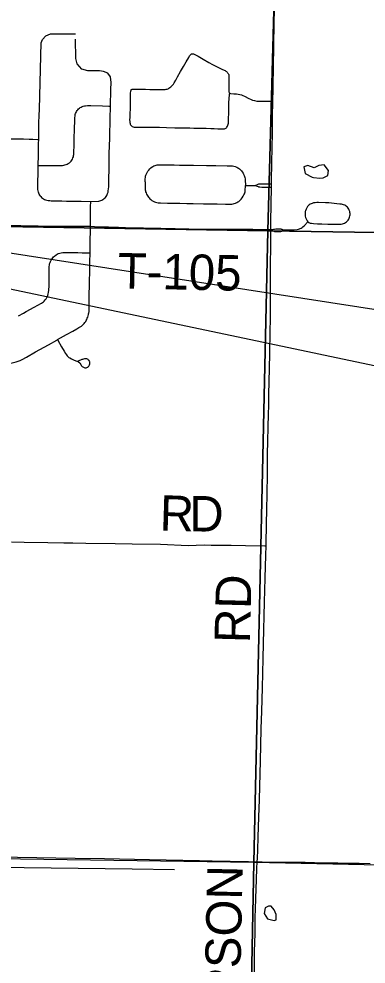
# Model space of a CAD drawing. Extents: x 0 to 34, y 0 to 22.
# Drawn here: x 5.051 to 5.608, y 14.756 to 16.271 of the extents above; entities that cross this region are included whole.
import ezdxf

# ---------------------------------------------------------------- set-up
doc = ezdxf.new("R2010")
doc.units = 0
for name, color, linetype in [('GM_X_Corporation', 7, 'Continuous'), ('GM_X_County_Road', 7, 'Continuous'), ('GM_X_Minor_Lake', 7, 'Continuous'), ('GM_X_Minor_River', 7, 'Continuous'), ('GM_X_Township_Road', 7, 'Continuous'), ('GM_X_Township_Road_Text', 7, 'Continuous'), ('SH_Text', 7, 'Continuous')]:
    doc.layers.add(name, color=color, linetype=linetype)

msp = doc.modelspace()

# ---------------------------------------------------------------- linework, layer by layer
at = {"layer": 'GM_X_Corporation'}
for points in [[(4.4576, 16.9688), (5.4784, 16.9512), (5.4509, 15.9313), (4.4354, 15.9477)], [(5.4784, 16.9512), (6.4745, 16.9262), (6.4581, 15.916), (5.4509, 15.9313)], [(4.4354, 15.9477), (5.4509, 15.9313), (5.428, 14.9189), (4.4167, 14.9334)], [(5.4509, 15.9313), (6.4581, 15.916), (6.4397, 14.8975), (5.428, 14.9189)], [(4.4016, 14.1), (5.4122, 14.1), (5.428, 14.9189), (4.4167, 14.9334)], [(5.4122, 14.1), (6.4222, 14.1), (6.4397, 14.8975), (5.428, 14.9189)]]:
    msp.add_lwpolyline(points, close=True, dxfattribs=at)
at = {"layer": 'GM_X_County_Road'}
for points in [[(4.6352, 14.9342), (4.6708, 14.9336), (4.6925, 14.9331), (4.7124, 14.9327), (4.7317, 14.9325), (4.7628, 14.932), (4.8187, 14.9312), (4.8448, 14.9309), (4.8865, 14.9303), (4.9226, 14.9299), (4.9574, 14.9294), (5.0171, 14.9284), (5.0494, 14.9276), (5.1414, 14.9258), (5.1886, 14.9251), (5.2607, 14.9239), (5.3409, 14.922), (5.3614, 14.9216), (5.4198, 14.9204), (5.4337, 14.9202)], [(5.4337, 14.9202), (5.4416, 14.9201), (5.459, 14.9197), (5.4764, 14.9195), (5.4938, 14.9193), (5.5106, 14.9192), (5.5404, 14.9186), (5.5628, 14.9184), (5.5758, 14.9181), (5.597, 14.9176), (5.615, 14.9172)]]:
    msp.add_lwpolyline(points, dxfattribs=at)
at = {"layer": 'GM_X_Minor_Lake'}
for p, q in [((5.5239, 16.0167), (5.5339, 16.0159)), ((5.4639, 14.8356), (5.4606, 14.8429))]:
    msp.add_line(p, q, dxfattribs=at)
for points in [[(5.5339, 16.0159), (5.5397, 16.0161), (5.5469, 16.0198), (5.5481, 16.0282), (5.5411, 16.037), (5.5327, 16.0359), (5.5248, 16.0322), (5.5146, 16.0362), (5.5082, 16.0336), (5.5107, 16.0233), (5.5216, 16.0171), (5.5239, 16.0167)], [(5.4606, 14.8429), (5.4561, 14.849), (5.4519, 14.8491), (5.4462, 14.8461), (5.4446, 14.8374), (5.4502, 14.8286), (5.4611, 14.8258), (5.4641, 14.8269), (5.4639, 14.8356)]]:
    msp.add_lwpolyline(points, dxfattribs=at)
at = {"layer": 'GM_X_Minor_River'}
msp.add_lwpolyline([(4.5825, 14.9176), (4.8159, 14.9147), (4.9205, 14.913), (5.0599, 14.9109), (5.2329, 14.9087), (5.3008, 14.9079)], dxfattribs=at)
at = {"layer": 'GM_X_Township_Road'}
for p, q in [((5.1982, 16.1312), (5.1986, 16.1577)), ((5.4148, 16.0038), (5.4305, 16.0039))]:
    msp.add_line(p, q, dxfattribs=at)
for points in [[(5.4589, 16.1391), (5.4593, 16.1587), (5.4598, 16.1991), (5.4602, 16.2227), (5.461, 16.2687), (5.4617, 16.2942), (5.4621, 16.3079), (5.4623, 16.3178), (5.4625, 16.334), (5.4626, 16.3496), (5.4629, 16.3682), (5.4631, 16.3769), (5.4633, 16.383), (5.4638, 16.3872), (5.4646, 16.3905), (5.468, 16.4019)], [(5.0831, 16.0778), (5.0833, 16.0954), (5.0836, 16.1041), (5.0841, 16.1159), (5.0844, 16.126), (5.0872, 16.2325), (5.0891, 16.238), (5.0948, 16.2438), (5.102, 16.2468), (5.1422, 16.2468)], [(5.1986, 16.1577), (5.1993, 16.1688), (5.1983, 16.1779), (5.194, 16.1842), (5.1872, 16.1867), (5.1809, 16.1877), (5.1619, 16.1876), (5.1525, 16.1901), (5.1449, 16.1989), (5.1426, 16.2076), (5.1423, 16.2383)], [(5.2315, 16.1576), (5.2329, 16.1581), (5.2344, 16.1584), (5.2363, 16.1584), (5.2385, 16.1584), (5.2447, 16.1583), (5.2484, 16.1582), (5.2509, 16.1582), (5.2547, 16.1581), (5.2615, 16.158), (5.2683, 16.1578), (5.2733, 16.1577), (5.2782, 16.1577), (5.2832, 16.1577), (5.2858, 16.1578), (5.2877, 16.1581), (5.289, 16.1584), (5.2909, 16.1591), (5.292, 16.1597), (5.2937, 16.1608), (5.2952, 16.162), (5.2966, 16.1634), (5.2979, 16.1648), (5.2991, 16.1664), (5.3005, 16.1685), (5.3029, 16.1729), (5.3059, 16.1783), (5.3106, 16.1864), (5.3152, 16.1945), (5.3174, 16.1983), (5.3195, 16.202), (5.3237, 16.2091), (5.3251, 16.2115), (5.326, 16.2127), (5.327, 16.2137), (5.3276, 16.2142), (5.3282, 16.2147), (5.3293, 16.2152)], [(5.3293, 16.2152), (5.3303, 16.2151), (5.331, 16.215), (5.3317, 16.2148), (5.3324, 16.2145), (5.3335, 16.214), (5.3344, 16.2135), (5.3388, 16.2111), (5.3468, 16.2063), (5.356, 16.2012), (5.362, 16.1979), (5.3736, 16.1919), (5.378, 16.1898), (5.382, 16.188), (5.3832, 16.1873), (5.3843, 16.1866), (5.3853, 16.1857), (5.3862, 16.1847), (5.387, 16.1836), (5.3876, 16.1823), (5.3879, 16.1817), (5.3881, 16.1803), (5.3882, 16.1784), (5.3881, 16.1715), (5.3881, 16.1647), (5.3881, 16.1603), (5.3881, 16.1566), (5.3882, 16.1548), (5.3883, 16.1538), (5.3887, 16.1528), (5.3896, 16.1518)], [(5.2315, 16.1576), (5.2308, 16.1564), (5.2304, 16.1547), (5.2301, 16.1526), (5.2298, 16.1458), (5.2297, 16.1415), (5.2297, 16.1371), (5.2296, 16.1315), (5.2296, 16.1272), (5.2294, 16.119), (5.2293, 16.116), (5.2292, 16.1128), (5.229, 16.1091), (5.2291, 16.1067), (5.2294, 16.105), (5.2298, 16.1033), (5.2301, 16.1022), (5.2306, 16.1012), (5.2312, 16.1002), (5.232, 16.0994), (5.2332, 16.0985), (5.2348, 16.0979), (5.2365, 16.0976), (5.2412, 16.0975), (5.2458, 16.0974), (5.2526, 16.0973), (5.2625, 16.0972), (5.2718, 16.0973), (5.2768, 16.0973), (5.288, 16.0968), (5.3017, 16.0965), (5.3116, 16.0964), (5.3185, 16.0962), (5.3253, 16.0961), (5.3321, 16.096), (5.3408, 16.0959), (5.352, 16.0957), (5.3595, 16.0955), (5.3645, 16.0953), (5.3707, 16.0949), (5.3787, 16.0945), (5.3799, 16.0945), (5.3814, 16.0948), (5.3824, 16.0953), (5.3834, 16.0959), (5.3842, 16.0966), (5.3849, 16.0974), (5.3858, 16.0989), (5.3866, 16.1005), (5.3872, 16.1022), (5.3875, 16.1039), (5.3877, 16.1056), (5.3878, 16.1081), (5.3882, 16.123), (5.3882, 16.1292), (5.3882, 16.1325), (5.3881, 16.1354), (5.3883, 16.1387), (5.3884, 16.1411), (5.3886, 16.1452), (5.389, 16.1478), (5.3894, 16.1506), (5.3896, 16.1518)], [(5.3896, 16.1518), (5.391, 16.1512), (5.3964, 16.151), (5.4002, 16.1507), (5.4033, 16.1503), (5.4058, 16.1498), (5.4083, 16.1491), (5.4107, 16.1482), (5.4135, 16.1469), (5.4201, 16.1433), (5.4229, 16.1421), (5.424, 16.1416), (5.4263, 16.1408), (5.4292, 16.14), (5.4328, 16.1393), (5.4364, 16.139), (5.4401, 16.1389), (5.445, 16.1389), (5.4513, 16.139), (5.4589, 16.1391)], [(5.4564, 16.0013), (5.4565, 16.0064), (5.4567, 16.0131), (5.4571, 16.0386), (5.4577, 16.0666), (5.458, 16.0859), (5.4584, 16.1139), (5.4589, 16.1391)], [(5.0824, 16.0361), (5.0853, 16.0361), (5.1008, 16.0362), (5.1183, 16.036), (5.1214, 16.0361), (5.1234, 16.0364), (5.1253, 16.0368), (5.1271, 16.0374), (5.1289, 16.0382), (5.1306, 16.0391), (5.1323, 16.0402), (5.1337, 16.0415), (5.1351, 16.043), (5.1363, 16.0446), (5.1372, 16.0463), (5.138, 16.048), (5.1387, 16.0499), (5.1392, 16.0518), (5.1395, 16.0537), (5.1397, 16.0569), (5.1399, 16.0687), (5.1401, 16.0749), (5.1403, 16.0825), (5.1405, 16.0912), (5.1406, 16.0954), (5.1409, 16.1078), (5.1411, 16.1127), (5.1414, 16.1151), (5.1418, 16.1175), (5.1424, 16.1192), (5.143, 16.1209), (5.1438, 16.1224), (5.1448, 16.1239), (5.1459, 16.1253), (5.1471, 16.1266), (5.1485, 16.1277), (5.1499, 16.1288), (5.1514, 16.1297), (5.153, 16.1305), (5.1547, 16.1311), (5.1564, 16.1315), (5.1582, 16.1318), (5.1612, 16.1319), (5.1668, 16.132), (5.1854, 16.1316), (5.1955, 16.1313), (5.1982, 16.1312)], [(5.1666, 15.9783), (5.1795, 15.9788), (5.1812, 15.9792), (5.1829, 15.9798), (5.1845, 15.9805), (5.1861, 15.9814), (5.1875, 15.9824), (5.1889, 15.9836), (5.1901, 15.9849), (5.1912, 15.9862), (5.1922, 15.9877), (5.1931, 15.9893), (5.1937, 15.9909), (5.1944, 15.9932), (5.1948, 15.9956), (5.1952, 15.9986), (5.1954, 16.0017), (5.1958, 16.0191), (5.196, 16.0259), (5.196, 16.029), (5.1962, 16.0411), (5.1964, 16.0552), (5.1971, 16.08), (5.198, 16.1129), (5.1982, 16.1291), (5.1982, 16.1312)], [(5.0264, 16.079), (5.0282, 16.079), (5.0369, 16.0788), (5.0437, 16.0788), (5.0522, 16.0786)], [(5.0522, 16.0786), (5.0585, 16.0785), (5.0676, 16.0782), (5.074, 16.0781), (5.0814, 16.0778), (5.0831, 16.0778)], [(5.0824, 16.0361), (5.0824, 16.0388), (5.0826, 16.05), (5.083, 16.0711), (5.0831, 16.0778)], [(5.0864, 15.9864), (5.0849, 15.9885), (5.0839, 15.9901), (5.0831, 15.9918), (5.0826, 15.9935), (5.0822, 15.9954), (5.0819, 15.9974), (5.0816, 16.0009), (5.0816, 16.0053), (5.0822, 16.0276), (5.0824, 16.0361)], [(5.2538, 16.0098), (5.2539, 16.0115), (5.2539, 16.0145), (5.2542, 16.0169), (5.2545, 16.0187), (5.255, 16.0204), (5.2559, 16.0226), (5.2569, 16.0248), (5.2582, 16.0268), (5.2597, 16.0287), (5.2613, 16.0305), (5.263, 16.0321), (5.2649, 16.0336), (5.2664, 16.0345), (5.268, 16.0353), (5.2697, 16.036), (5.2714, 16.0365), (5.2731, 16.0368), (5.2755, 16.0371), (5.2792, 16.0373), (5.2841, 16.0372), (5.2925, 16.037), (5.3002, 16.0368), (5.3089, 16.0367), (5.3313, 16.0364), (5.3523, 16.0361), (5.3673, 16.0359), (5.3853, 16.0357), (5.3909, 16.0356), (5.3939, 16.0353), (5.3962, 16.0348), (5.3985, 16.0342), (5.4007, 16.0333), (5.4023, 16.0324), (5.4038, 16.0315), (5.4052, 16.0304), (5.4066, 16.0292), (5.4082, 16.0275), (5.4097, 16.0256), (5.4111, 16.0236), (5.4119, 16.0221), (5.4129, 16.0199), (5.4135, 16.0182), (5.4139, 16.0165), (5.4143, 16.0147), (5.4145, 16.0128), (5.4148, 16.0038)], [(5.2538, 16.0098), (5.2539, 16.0033), (5.254, 15.9997), (5.2541, 15.9972), (5.2543, 15.9955), (5.2547, 15.9937), (5.2553, 15.9921), (5.2563, 15.9899), (5.2581, 15.9867), (5.2591, 15.9852), (5.2602, 15.9839), (5.2614, 15.9826), (5.2628, 15.9814), (5.2647, 15.98), (5.2668, 15.9789), (5.269, 15.9779), (5.2707, 15.9772), (5.2724, 15.9768), (5.2747, 15.9764), (5.2784, 15.9761), (5.2895, 15.9757), (5.3007, 15.9757), (5.3093, 15.9755), (5.3206, 15.9752), (5.3309, 15.975), (5.3473, 15.9748), (5.364, 15.9746), (5.3696, 15.9746), (5.3827, 15.9742), (5.3907, 15.9741), (5.393, 15.9742), (5.3949, 15.9745), (5.3966, 15.9749), (5.3989, 15.9757), (5.4011, 15.9766), (5.4027, 15.9775), (5.4041, 15.9784), (5.4055, 15.9795), (5.4068, 15.9808), (5.408, 15.9821), (5.4095, 15.984), (5.4112, 15.9866), (5.4123, 15.9887), (5.413, 15.9903), (5.4136, 15.992), (5.4141, 15.9937), (5.4143, 15.9954), (5.4148, 16.0038)], [(5.4305, 16.0039), (5.4354, 16.0061), (5.4365, 16.0065), (5.4372, 16.0066), (5.4379, 16.0066), (5.4404, 16.0066), (5.4441, 16.0066), (5.4506, 16.0065), (5.4565, 16.0064)], [(5.4305, 16.0039), (5.4351, 16.0021), (5.4359, 16.0018), (5.4366, 16.0016), (5.4378, 16.0016), (5.441, 16.0015), (5.4465, 16.0015), (5.4508, 16.0014), (5.4564, 16.0013)], [(5.4554, 15.9333), (5.4554, 15.946), (5.4564, 16.0013)], [(5.0864, 15.9864), (5.0878, 15.9849), (5.0894, 15.9836), (5.0909, 15.9825), (5.0925, 15.9816), (5.0943, 15.9809), (5.0961, 15.9804), (5.0985, 15.98), (5.101, 15.9797), (5.1034, 15.9795), (5.1103, 15.9793), (5.1158, 15.9792), (5.1202, 15.9791), (5.1277, 15.979), (5.1376, 15.9788), (5.1445, 15.9787), (5.1513, 15.9787), (5.1666, 15.9783)], [(5.1659, 15.9386), (5.166, 15.9404), (5.1664, 15.9519), (5.1664, 15.9572), (5.1665, 15.9648), (5.1665, 15.9696), (5.1666, 15.9783)], [(5.5151, 15.9458), (5.5166, 15.9448), (5.5186, 15.9438), (5.5207, 15.9434), (5.5237, 15.943), (5.5305, 15.9425), (5.5374, 15.9423), (5.5467, 15.9421), (5.556, 15.9418), (5.5591, 15.9419), (5.5634, 15.942), (5.5665, 15.942), (5.5684, 15.9422), (5.5702, 15.9425), (5.572, 15.943), (5.5737, 15.9437), (5.5754, 15.9446), (5.5769, 15.9457), (5.5782, 15.9469), (5.5794, 15.9484), (5.5804, 15.9499), (5.5813, 15.9516), (5.5819, 15.9533), (5.5824, 15.9552), (5.5826, 15.957), (5.5826, 15.9589), (5.5824, 15.9607), (5.582, 15.9625), (5.5814, 15.9643), (5.5806, 15.966), (5.5796, 15.9675), (5.5784, 15.969), (5.5771, 15.9703), (5.5756, 15.9714), (5.574, 15.9724), (5.5723, 15.9731), (5.5705, 15.9736), (5.5687, 15.974), (5.5662, 15.9742), (5.5615, 15.9747), (5.5483, 15.976), (5.5434, 15.9763), (5.5322, 15.9767), (5.5291, 15.9767), (5.5264, 15.9764), (5.5238, 15.9759), (5.522, 15.9753), (5.5202, 15.9746), (5.5185, 15.9738), (5.5169, 15.9728), (5.5155, 15.9716), (5.5144, 15.9702), (5.5137, 15.9691), (5.5121, 15.9658), (5.5111, 15.9635), (5.5108, 15.9623), (5.5105, 15.9604), (5.5104, 15.9585), (5.5105, 15.9566), (5.5107, 15.9547), (5.5112, 15.9529), (5.5116, 15.9517), (5.5127, 15.9495), (5.514, 15.9474), (5.5151, 15.9458)], [(5.0242, 15.9401), (5.032, 15.94), (5.0544, 15.9396), (5.0823, 15.9391), (5.0991, 15.9388), (5.1091, 15.9388), (5.1191, 15.9388), (5.1358, 15.9387), (5.1443, 15.9387), (5.1659, 15.9386)], [(5.1659, 15.9386), (5.1651, 15.9085), (5.1649, 15.8958)], [(5.1659, 15.9386), (5.1728, 15.9383), (5.1859, 15.9379), (5.1949, 15.9376), (5.2053, 15.9372), (5.2109, 15.937), (5.2223, 15.9368), (5.2343, 15.9363), (5.251, 15.9359), (5.279, 15.9354), (5.302, 15.9351), (5.3461, 15.9342), (5.3629, 15.9341), (5.3764, 15.9338), (5.3854, 15.9338), (5.4006, 15.934), (5.4089, 15.934), (5.4191, 15.9338), (5.4265, 15.9337), (5.4381, 15.9336), (5.4478, 15.9335), (5.4554, 15.9333)], [(5.4756, 15.9329), (5.4792, 15.9329), (5.4828, 15.9329), (5.4866, 15.9329), (5.4928, 15.933), (5.4978, 15.9334), (5.4997, 15.9337), (5.5016, 15.9343), (5.5028, 15.9349), (5.504, 15.9355), (5.5056, 15.9366), (5.507, 15.9378), (5.5089, 15.9395), (5.5151, 15.9458)], [(5.4478, 15.4265), (5.4479, 15.431), (5.4489, 15.4875), (5.4494, 15.5068), (5.45, 15.5441), (5.4504, 15.5727), (5.4518, 15.638), (5.4521, 15.651), (5.4525, 15.6697), (5.4528, 15.689), (5.4537, 15.7337), (5.4545, 15.771), (5.4547, 15.7891), (5.4552, 15.8501), (5.4554, 15.9333)], [(5.4554, 15.9333), (5.4598, 15.9341), (5.4608, 15.9342), (5.4615, 15.9342), (5.4633, 15.9343), (5.466, 15.9343)], [(5.4554, 15.9333), (5.4592, 15.9312), (5.4603, 15.9307), (5.4613, 15.9304), (5.4653, 15.9304)], [(5.4653, 15.9304), (5.4713, 15.9304), (5.4719, 15.9306), (5.4726, 15.9308), (5.4756, 15.9329)], [(5.466, 15.9343), (5.4687, 15.9343), (5.4705, 15.9343), (5.4715, 15.9343), (5.4723, 15.9341), (5.473, 15.9339), (5.4756, 15.9329)], [(5.0505, 15.7952), (5.0585, 15.7994), (5.0628, 15.8018), (5.0759, 15.809), (5.0878, 15.8156), (5.0894, 15.8165), (5.0908, 15.8176), (5.0921, 15.8188), (5.0937, 15.8206), (5.0951, 15.8225), (5.0964, 15.8245), (5.0972, 15.8261), (5.0978, 15.8278), (5.0984, 15.8301), (5.0988, 15.8325), (5.0992, 15.8361), (5.0994, 15.8384), (5.0997, 15.8411), (5.0999, 15.8472), (5.0999, 15.8515), (5.0998, 15.8577), (5.0999, 15.8646), (5.1001, 15.874), (5.1004, 15.8765), (5.1007, 15.8784), (5.1013, 15.8803), (5.102, 15.8821), (5.1032, 15.8844), (5.1045, 15.8866), (5.1057, 15.8882), (5.107, 15.8896), (5.1083, 15.8908), (5.111, 15.8928), (5.1127, 15.8938), (5.1144, 15.8947), (5.1169, 15.8955), (5.1194, 15.8961), (5.1219, 15.8965), (5.1245, 15.8967), (5.1326, 15.8967), (5.1399, 15.8965), (5.1459, 15.8963), (5.1526, 15.8962), (5.162, 15.8959), (5.1649, 15.8958)], [(5.1649, 15.8958), (5.1645, 15.8811), (5.1644, 15.8662), (5.1641, 15.85), (5.1638, 15.8226), (5.1635, 15.8114), (5.1633, 15.8026), (5.1632, 15.799)], [(5.1132, 15.757), (5.1278, 15.7652), (5.1377, 15.7705), (5.1442, 15.7741), (5.1476, 15.7761), (5.1496, 15.7773), (5.1517, 15.7787), (5.1532, 15.7799), (5.1551, 15.7817), (5.1563, 15.7829), (5.1574, 15.7844), (5.1586, 15.7862), (5.1595, 15.7876), (5.1603, 15.7894), (5.1611, 15.7911), (5.162, 15.7931), (5.1625, 15.7951), (5.1629, 15.797), (5.1632, 15.799)], [(4.9686, 15.7188), (4.9816, 15.7187), (4.9895, 15.7186), (4.9977, 15.7185), (5.0016, 15.7184), (5.0067, 15.7183), (5.013, 15.7182), (5.0192, 15.7181), (5.0238, 15.718), (5.027, 15.7179), (5.0301, 15.7182), (5.0345, 15.7186), (5.0382, 15.7192), (5.0425, 15.7201), (5.0468, 15.7213), (5.0504, 15.7224), (5.0533, 15.7236), (5.0568, 15.7252), (5.0634, 15.7288), (5.078, 15.7371), (5.0986, 15.7487), (5.1121, 15.7563), (5.1132, 15.757)], [(5.1132, 15.757), (5.1139, 15.7558), (5.1199, 15.7452), (5.1239, 15.7382), (5.1261, 15.7345), (5.1276, 15.7325), (5.1287, 15.731), (5.13, 15.7297), (5.1315, 15.7285), (5.133, 15.7275), (5.1357, 15.726), (5.138, 15.7249), (5.1403, 15.724), (5.1444, 15.7226), (5.1461, 15.7219), (5.1472, 15.7212), (5.1489, 15.7195), (5.1512, 15.7158), (5.152, 15.7148), (5.1528, 15.7139), (5.1538, 15.7132), (5.1549, 15.7126), (5.1561, 15.7121), (5.1572, 15.7119), (5.1584, 15.7118), (5.1595, 15.7119), (5.1604, 15.7121), (5.1614, 15.7126), (5.1622, 15.713), (5.163, 15.7138), (5.1636, 15.7146), (5.1642, 15.7155), (5.1647, 15.7167), (5.1651, 15.718), (5.1652, 15.7195), (5.1652, 15.7204), (5.165, 15.7213), (5.1647, 15.7221), (5.1641, 15.7232), (5.1632, 15.7241), (5.1624, 15.7249), (5.1613, 15.7256), (5.1603, 15.726), (5.1594, 15.7262), (5.1582, 15.7263), (5.1566, 15.7261), (5.155, 15.7258), (5.1535, 15.7253), (5.1522, 15.7249), (5.1502, 15.7241), (5.1485, 15.7235), (5.1473, 15.723), (5.146, 15.7225)], [(5.0393, 15.4327), (5.0598, 15.4324), (5.0977, 15.4318), (5.1232, 15.4315), (5.1381, 15.4313), (5.1585, 15.4309), (5.2058, 15.4301), (5.233, 15.4297), (5.2785, 15.429), (5.3228, 15.4272), (5.3488, 15.4279), (5.36, 15.4276), (5.3918, 15.4273), (5.4148, 15.4268), (5.4459, 15.4265), (5.4478, 15.4265)], [(5.4337, 14.9202), (5.434, 14.9256), (5.4345, 14.9387), (5.4352, 14.9598), (5.4363, 14.9915), (5.4372, 15.0201), (5.4376, 15.0406), (5.4388, 15.0817), (5.4395, 15.1071), (5.4402, 15.1333), (5.441, 15.1612), (5.4422, 15.1991), (5.4433, 15.2458), (5.4438, 15.27), (5.4456, 15.3359), (5.4466, 15.3744), (5.4474, 15.4117), (5.4478, 15.4265)], [(5.4213, 14.4156), (5.4215, 14.4215), (5.4222, 14.45), (5.4236, 14.4992), (5.4253, 14.5456), (5.4255, 14.5657), (5.4257, 14.5877), (5.4262, 14.6113), (5.4271, 14.6349), (5.4277, 14.6504), (5.4282, 14.6696), (5.4292, 14.7175), (5.4293, 14.7363), (5.4294, 14.7506), (5.4295, 14.7766), (5.4298, 14.7902), (5.4301, 14.8052), (5.4306, 14.8313), (5.431, 14.8443), (5.4315, 14.8611), (5.4325, 14.8916), (5.4332, 14.9093), (5.4337, 14.9202)]]:
    msp.add_lwpolyline(points, dxfattribs=at)
at = {"layer": 'SH_Text'}
msp.add_lwpolyline([(3.9929, 16.0574), (9.3797, 15.2243), (9.3797, 14.9242)], close=True, dxfattribs=at)

# ---------------------------------------------------------------- texts
at = {"layer": 'GM_X_Township_Road_Text'}
for s, height, rotation, p in [('T-105', 0.05682, 358.8819, (5.2095, 15.8391)), ('R', 0.0568, 358.3254, (5.2767, 15.4509)), ('D', 0.0568, 359.7008, (5.3248, 15.4495)), ('RD', 0.05682, 88.5194, (5.4218, 15.27)), ('THOMPSON', 0.05682, 88.7689, (5.401, 14.4748))]:
    msp.add_text(s, height=height, rotation=rotation, dxfattribs=at).set_placement(p)

doc.saveas('drawing.dxf')
